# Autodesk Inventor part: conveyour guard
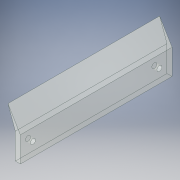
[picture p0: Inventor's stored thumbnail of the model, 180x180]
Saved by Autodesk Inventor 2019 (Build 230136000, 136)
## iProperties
Created: 2021-07
Part Number: conveyour guard
Material: Glass
Document SubType Name: Modeling
Designer: Avinash
Density: 2.18 g/cm^3
Appearance: Clear
Author: Avinash
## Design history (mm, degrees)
sketch "Sketch1"
  geometry: L1 (0, 0)-(-10, 0); L2 (-10, 0)-(-10, 51.217); L3 (0, 50)-(0, 0); L4 (-24.583, 91.285)-(-10, 51.217); L5 (-24.583, 91.285)-(0, 50)
  constraints: 10 end point, 1 horizontal, 1 parallel, 1 perpendicular
  dimensions: "d1" = 50 distance of L3.start L1.start; "d2" = 160 deg angle of L2 L4
extrude "Extrusion1" new body sketch "Sketch1" distance "d3" = 300; taper "d4" = 0 deg
sketch "Sketch6"
  geometry: L1 (0, 51.217)-(300, 51.217) reference; L2 (0, 0)-(0, 51.217) reference; L3 (300, 51.217)-(300, 0) reference; C1 r 5 at (25, 26.217); C2 r 5 at (275, 26.217)
  constraints: 2 centre point
  dimensions: "d5" = 10 diameter of C1; "d6" = 10 diameter of C2; "d7" = 25 distance from line of L1 C1.centre; "d8" = 25 distance from line of L2 C1.centre; "d9" = 25 distance from line of L1 C2.centre; "d10" = 25 distance from line of L3 C2.centre
extrude "Extrusion2" cut sketch "Sketch6" distance "d11" = 10; taper "d12" = 0 deg
body "Solid1"
